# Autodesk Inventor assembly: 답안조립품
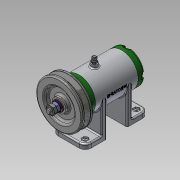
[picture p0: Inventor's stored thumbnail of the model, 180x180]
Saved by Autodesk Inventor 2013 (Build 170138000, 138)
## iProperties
Created: 2017-02
Part Number: 답안조립품
Document SubType Name: Assembly
Designer: hana-cad19
Author: hana-cad19
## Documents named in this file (16)
- C:\Documents and Settings\hana-cad19\바탕 화면\470208V1017\답안조립품.iam
- C:\Documents and Settings\hana-cad19\바탕 화면\470208V1017\1.본체.ipt
- C:\Documents and Settings\hana-cad19\바탕 화면\470208V1017\베어링 15 x 32 x 9.ipt
- C:\Documents and Settings\hana-cad19\바탕 화면\470208V1017\앞커버.ipt
- C:\Documents and Settings\hana-cad19\바탕 화면\470208V1017\오일 실 15 25 7.ipt
- C:\Documents and Settings\hana-cad19\바탕 화면\470208V1017\볼트 M4 x 12.ipt
- C:\Documents and Settings\hana-cad19\바탕 화면\470208V1017\축.ipt
- C:\Documents and Settings\hana-cad19\바탕 화면\470208V1017\키 3 x 3 x 12.ipt
- C:\Documents and Settings\hana-cad19\바탕 화면\470208V1017\V벨트풀리.ipt
- C:\Documents and Settings\hana-cad19\바탕 화면\470208V1017\와셔 8x17.ipt
- C:\Documents and Settings\hana-cad19\바탕 화면\470208V1017\스프링와셔 8.ipt
- C:\Documents and Settings\hana-cad19\바탕 화면\470208V1017\너트 M 8.ipt
- C:\Documents and Settings\hana-cad19\바탕 화면\470208V1017\뒤커버.ipt
- C:\Documents and Settings\hana-cad19\바탕 화면\470208V1017\니플 M 6 x 0.75.ipt
- C:\Documents and Settings\hana-cad19\바탕 화면\470208V1017\와셔 6x11.5.ipt
- C:\Documents and Settings\hana-cad19\바탕 화면\470208V1017\볼트 M 6 x 8.ipt
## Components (12 placed, 4 different names)
1. 1.본체:1
2. KS B 2023 6002 - 15 x 32 x 9:1
3. V벨트풀리:1 — 각도:2
4. KS B 2023 6002 - 15 x 32 x 9:2
5. ISO 4762 M4 x 12:1
6. ISO 4762 M4 x 12:2
7. ISO 4762 M4 x 12:3
8. ISO 4762 M4 x 12:4
9. ISO 4762 M4 x 12:5
10. ISO 4762 M4 x 12:6
11. ISO 4762 M4 x 12:7
12. ISO 4762 M4 x 12:8
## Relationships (1: Angle 1)
- 각도:2 [Angle]: V벨트풀리:1
